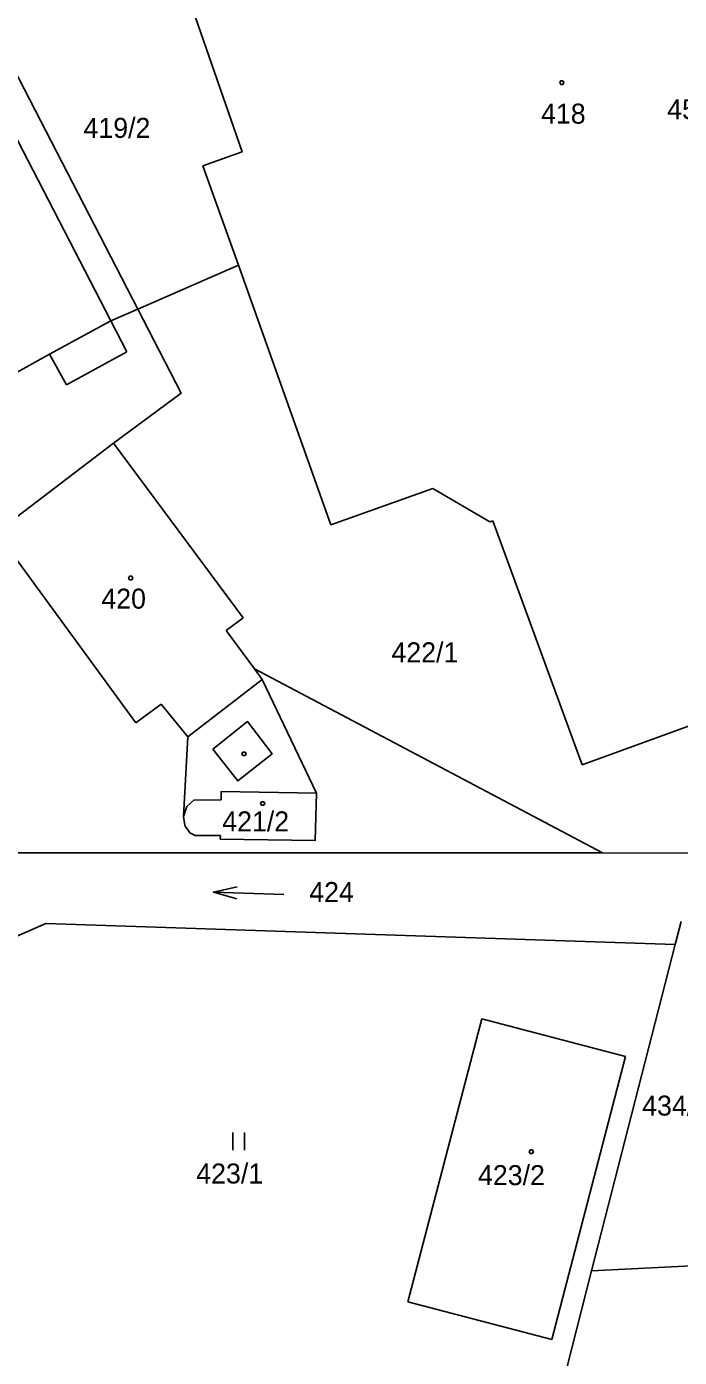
# Model space of a CAD drawing. Extents: x -609861 to -605046, y -1120287 to -1116307.
# Drawn here: x -607304.7 to -607249.2, y -1119513.1 to -1119400 of the extents above; entities that cross this region are included whole.
import ezdxf

# ---------------------------------------------------------------- set-up
doc = ezdxf.new("R2010")
doc.units = 0
for name, color, linetype in [('Vrstva 1', 7, 'Continuous'), ('Vrstva 2', 7, 'Continuous'), ('Vrstva 3', 7, 'Continuous'), ('Vrstva 4', 7, 'Continuous'), ('Vrstva 5', 7, 'Continuous'), ('Vrstva 7', 7, 'Continuous')]:
    doc.layers.add(name, color=color, linetype=linetype)

msp = doc.modelspace()

# ---------------------------------------------------------------- linework, layer by layer
at = {"layer": 'Vrstva 1'}
for p, q in [((-607307.24, -1119400.88), (-607295.27, -1119424.05)), ((-607289.72, -1119411.88), (-607286.4, -1119410.68)), ((-607289.72, -1119411.88), (-607286.71, -1119420.32)), ((-607295.27, -1119424.05), (-607286.71, -1119420.32)), ((-607286.71, -1119420.32), (-607278.85, -1119442.37)), ((-607297.57, -1119425.05), (-607295.27, -1119424.05)), ((-607297.57, -1119425.05), (-607296.21, -1119427.67)), ((-607302.76, -1119427.87), (-607318.99, -1119436.82)), ((-607301.32, -1119430.48), (-607302.76, -1119427.87)), ((-607296.21, -1119427.67), (-607301.32, -1119430.48)), ((-607307.28, -1119443.01), (-607297.34, -1119435.44)), ((-607297.34, -1119435.44), (-607286.3, -1119450.27)), ((-607278.85, -1119442.37), (-607270.16, -1119439.29)), ((-607270.16, -1119439.29), (-607265.32, -1119442.12)), ((-607265.32, -1119442.12), (-607265.07, -1119442.04)), ((-607265.07, -1119442.04), (-607257.48, -1119462.76)), ((-607295.44, -1119459.19), (-607307.28, -1119443.01)), ((-607286.3, -1119450.27), (-607287.75, -1119451.34)), ((-607287.75, -1119451.34), (-607285.35, -1119454.6)), ((-607285.35, -1119454.6), (-607284.7, -1119455.5)), ((-607285.35, -1119454.6), (-607255.74, -1119470.24)), ((-607284.7, -1119455.5), (-607291, -1119460.37)), ((-607280.08, -1119465.15), (-607284.7, -1119455.5)), ((-607237.63, -1119455.51), (-607257.48, -1119462.76)), ((-607293.27, -1119457.6), (-607295.44, -1119459.19)), ((-607291, -1119460.37), (-607293.27, -1119457.6)), ((-607291, -1119460.37), (-607291.38, -1119467.15)), ((-607255.74, -1119470.24), (-607307.42, -1119470.23)), ((-607247.44, -1119470.25), (-607255.74, -1119470.24)), ((-607306.77, -1119477.86), (-607303.08, -1119476.24)), ((-607303.08, -1119476.24), (-607249.56, -1119478.01)), ((-607249.06, -1119476.07), (-607249.56, -1119478.01)), ((-607249.56, -1119478.01), (-607256.67, -1119505.75)), ((-607272.29, -1119508.37), (-607266.02, -1119484.32)), ((-607266.02, -1119484.32), (-607253.78, -1119487.52)), ((-607253.78, -1119487.52), (-607260.05, -1119511.56)), ((-607256.67, -1119505.75), (-607259.3, -1119516.02)), ((-607256.67, -1119505.75), (-607247.03, -1119505.27)), ((-607260.05, -1119511.56), (-607272.29, -1119508.37))]:
    msp.add_line(p, q, dxfattribs=at)
for points in [[(-607286.4, -1119410.68), (-607291.32, -1119396.47), (-607287.45, -1119393.99)], [(-607295.27, -1119424.05), (-607291.58, -1119431.19), (-607297.34, -1119435.44)], [(-607291.38, -1119467.15), (-607291.27, -1119467.92), (-607290.85, -1119468.53), (-607290.39, -1119468.77), (-607288.24, -1119468.76), (-607288.25, -1119469.06), (-607280.17, -1119469.18), (-607280.08, -1119465.15)]]:
    msp.add_lwpolyline(points, dxfattribs=at)
at = {"layer": 'Vrstva 3'}
for p, q in [((-607282.832, -1119473.758), (-607288.828, -1119473.562)), ((-607287.19, -1119493.98), (-607287.19, -1119495.48)), ((-607286.19, -1119495.48), (-607286.19, -1119493.98))]:
    msp.add_line(p, q, dxfattribs=at)
msp.add_lwpolyline([(-607286.846, -1119474.127), (-607288.828, -1119473.562), (-607286.813, -1119473.128)], dxfattribs=at)
at = {"layer": 'Vrstva 4'}
for p, q in [((-607307.69, -1119405.46), (-607297.57, -1119425.05)), ((-607297.57, -1119425.05), (-607302.76, -1119427.87))]:
    msp.add_line(p, q, dxfattribs=at)
msp.add_lwpolyline([(-607288.88, -1119461.42), (-607285.93, -1119459.08), (-607283.85, -1119461.81), (-607286.76, -1119464.12)], close=True, dxfattribs=at)
msp.add_lwpolyline([(-607291.38, -1119467.15), (-607291.08, -1119466.3), (-607290.5, -1119465.77), (-607288.18, -1119465.72), (-607288.17, -1119465.01), (-607280.08, -1119465.15)], dxfattribs=at)
at = {"layer": 'Vrstva 5'}
for points in [[(-607259.11, -1119404.65), (-607259.02, -1119404.8), (-607259.11, -1119404.95), (-607259.29, -1119404.95), (-607259.38, -1119404.8), (-607259.29, -1119404.65)], [(-607295.78, -1119446.74), (-607295.69, -1119446.89), (-607295.78, -1119447.04), (-607295.96, -1119447.04), (-607296.05, -1119446.89), (-607295.96, -1119446.74)], [(-607286.14, -1119461.67), (-607286.05, -1119461.82), (-607286.14, -1119461.97), (-607286.32, -1119461.97), (-607286.41, -1119461.82), (-607286.32, -1119461.67)], [(-607284.55, -1119465.89), (-607284.46, -1119466.04), (-607284.55, -1119466.19), (-607284.73, -1119466.19), (-607284.82, -1119466.04), (-607284.73, -1119465.89)], [(-607261.71, -1119495.47), (-607261.62, -1119495.62), (-607261.71, -1119495.77), (-607261.89, -1119495.77), (-607261.98, -1119495.62), (-607261.89, -1119495.47)]]:
    msp.add_lwpolyline(points, close=True, dxfattribs=at)

# ---------------------------------------------------------------- texts
at = {"layer": 'Vrstva 2'}
for s, p in [('418', (-607260.973, -1119408.29)), ('419/2', (-607299.879, -1119409.5)), ('420', (-607298.363, -1119449.49)), ('422/1', (-607273.692, -1119454.05)), ('421/2', (-607288.082, -1119468.41)), ('424', (-607280.683, -1119474.41)), ('434/4', (-607252.373, -1119492.55)), ('423/1', (-607290.293, -1119498.32)), ('423/2', (-607266.333, -1119498.46))]:
    msp.add_text(s, height=1.7, dxfattribs=at).set_placement(p)
at = {"layer": 'Vrstva 7'}
msp.add_text('45/72', height=1.7, dxfattribs=at).set_placement((-607250.244, -1119407.91))

doc.saveas('drawing.dxf')
